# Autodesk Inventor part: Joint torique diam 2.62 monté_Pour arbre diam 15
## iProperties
Shininess: 64.0
Length Units: 11269
Angle Units: 11279
Time Units: 11290
Mass Units: 11283
Length Display Precision: 3
Angle Display Precision: 2
Compacted: True
Part Number: Joint torique diam 2.62 monté_Pour arbre diam 15
Document SubType Name: Modeling
Created: 2006-01
Material: Par défaut
Designer: riri
Density: 0.0
Volumn: 0.0
Area: 0.0
PropertySet Name: Model Information
Control State: 0
Master: False
Checked Out: False
Author: riri
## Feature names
1. Base1
